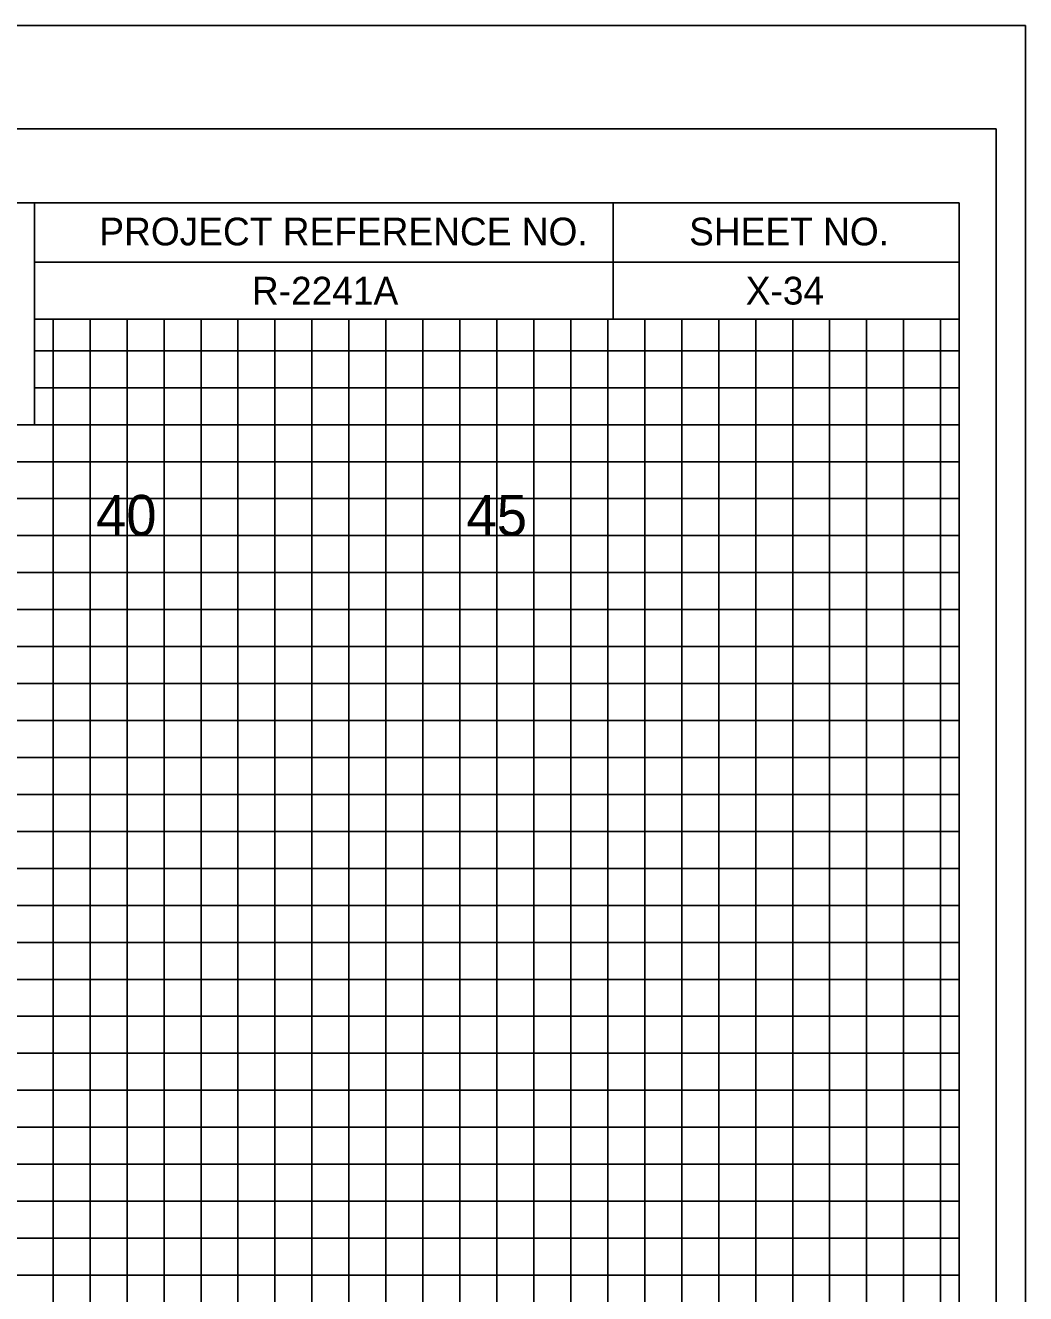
# Model space of a CAD drawing. Extents: x -4 to 103, y -2 to 6583.
# Drawn here: x 89.88 to 103.4, y 2387.47 to 2404.62 of the extents above; entities that cross this region are included whole.
import ezdxf

# ---------------------------------------------------------------- set-up
doc = ezdxf.new("R2010")
doc.units = 0
for name, color, linetype in [('Prop XS Offset Labels', 7, 'Continuous'), ('Prop XS Project Number', 7, 'Continuous'), ('Prop XS Sheet Number', 7, 'Continuous'), ('Sheet Cross Section CELL', 7, 'Continuous'), ('Sheet Cross Section Grid Major CELL', 7, 'Continuous'), ('Sheet Cross Section Grid Middle CELL', 7, 'Continuous'), ('Sheet Cutting Line CELL', 7, 'Continuous'), ('Sheet DOT Grid CELL', 7, 'Continuous'), ('Sheet Plot Border Inside CELL', 7, 'Continuous'), ('Sheet Plot Border Outside CELL', 7, 'Continuous')]:
    doc.layers.add(name, color=color, linetype=linetype)

msp = doc.modelspace()

# ---------------------------------------------------------------- linework, layer by layer
at = {"layer": 'Sheet Cross Section CELL'}
for p, q in [((90, 2402.225), (102.5, 2402.225)), ((90, 2402.225), (102.5, 2402.225)), ((97.825, 2400.65), (97.825, 2402.225)), ((101.875, 2402.225), (101.875, 2402.225)), ((102.5, 2402.225), (102.5, 2402.225)), ((102.5, 2400.65), (102.5, 2402.225)), ((102.5, 2402.225), (102.5, 2402.225)), ((102.5, 2402.225), (102.5, 2402.225)), ((102.5, 2400.65), (102.5, 2402.225)), ((90, 2401.425), (102.5, 2401.425)), ((90, 2400.65), (102.5, 2400.65)), ((99.4, 2400.65), (99.4, 2400.65)), ((99.4, 2400.65), (99.4, 2400.65))]:
    msp.add_line(p, q, dxfattribs=at)
for points in [[(102.5, 2402.225), (0, 2402.225), (0, 2337.225), (102.5, 2337.225)], [(83.75, 2402.225), (90, 2402.225), (90, 2399.225), (83.75, 2399.225)]]:
    msp.add_lwpolyline(points, close=True, dxfattribs=at)
at = {"layer": 'Sheet Cross Section Grid Major CELL'}
for points in [[(91.25, 2337.225), (91.25, 2400.65), (93.75, 2400.65), (93.75, 2337.225)], [(96.25, 2337.225), (96.25, 2400.65), (98.75, 2400.65), (98.75, 2337.225)], [(101.25, 2337.225), (101.25, 2400.65)], [(90, 2399.725), (102.5, 2399.725)], [(0, 2394.725), (102.5, 2394.725), (102.5, 2397.225), (0, 2397.225)], [(0, 2389.725), (102.5, 2389.725), (102.5, 2392.225), (0, 2392.225)]]:
    msp.add_lwpolyline(points, dxfattribs=at)
at = {"layer": 'Sheet Cross Section Grid Middle CELL'}
for points in [[(90.25, 2337.225), (90.25, 2400.65), (90.75, 2400.65), (90.75, 2337.225)], [(91.75, 2337.225), (91.75, 2400.65), (92.25, 2400.65), (92.25, 2337.225)], [(92.75, 2337.225), (92.75, 2400.65), (93.25, 2400.65), (93.25, 2337.225)], [(94.25, 2337.225), (94.25, 2400.65), (94.75, 2400.65), (94.75, 2337.225)], [(95.25, 2337.225), (95.25, 2400.65), (95.75, 2400.65), (95.75, 2337.225)], [(96.75, 2337.225), (96.75, 2400.65), (97.25, 2400.65), (97.25, 2337.225)], [(97.75, 2337.225), (97.75, 2400.65), (98.25, 2400.65), (98.25, 2337.225)], [(99.25, 2337.225), (99.25, 2400.65), (99.75, 2400.65), (99.75, 2337.225)], [(100.25, 2337.225), (100.25, 2400.65)], [(100.25, 2400.65), (100.75, 2400.65), (100.75, 2337.225), (101.75, 2337.225), (101.75, 2400.65), (102.25, 2400.65), (102.25, 2337.225)], [(102.5, 2399.225), (102.5, 2400.225), (90, 2400.225)], [(0, 2398.725), (102.5, 2398.725), (102.5, 2399.225), (0, 2399.225)], [(0, 2397.725), (102.5, 2397.725), (102.5, 2398.225), (0, 2398.225)], [(0, 2396.225), (102.5, 2396.225), (102.5, 2396.725), (0, 2396.725)], [(0, 2395.225), (102.5, 2395.225), (102.5, 2395.725), (0, 2395.725)], [(0, 2393.725), (102.5, 2393.725), (102.5, 2394.225), (0, 2394.225)], [(0, 2392.725), (102.5, 2392.725), (102.5, 2393.225), (0, 2393.225)], [(0, 2391.225), (102.5, 2391.225), (102.5, 2391.725), (0, 2391.725)], [(0, 2390.225), (102.5, 2390.225), (102.5, 2390.725), (0, 2390.725)], [(0, 2388.725), (102.5, 2388.725), (102.5, 2389.225), (0, 2389.225)], [(0, 2387.725), (102.5, 2387.725), (102.5, 2388.225), (0, 2388.225)]]:
    msp.add_lwpolyline(points, dxfattribs=at)
at = {"layer": 'Sheet Cutting Line CELL'}
msp.add_line((-3.5, 2404.625), (103.4, 2404.625), dxfattribs=at)
at = {"layer": 'Sheet DOT Grid CELL'}
for p, q in [((91.25, 2337.225), (91.25, 2400.65)), ((93.75, 2337.225), (93.75, 2400.65)), ((96.25, 2337.225), (96.25, 2400.65)), ((98.75, 2337.225), (98.75, 2400.65)), ((101.25, 2337.225), (101.25, 2400.65)), ((90, 2399.725), (102.5, 2399.725)), ((0, 2397.225), (102.5, 2397.225)), ((0, 2394.725), (102.5, 2394.725)), ((0, 2392.225), (102.5, 2392.225)), ((0, 2389.725), (102.5, 2389.725))]:
    msp.add_line(p, q, dxfattribs=at)
at = {"layer": 'Sheet Plot Border Inside CELL'}
msp.add_lwpolyline([(103, 2403.225), (-2.8, 2403.225), (-2.8, 2336.225), (103, 2336.225)], close=True, dxfattribs=at)
at = {"layer": 'Sheet Plot Border Outside CELL'}
msp.add_lwpolyline([(103.4, 2404.625), (-3.5, 2404.625), (-3.5, 2334.8), (103.4, 2334.8)], close=True, dxfattribs=at)

# ---------------------------------------------------------------- texts
at = {"layer": 'Prop XS Offset Labels'}
for s, p in [('40', (90.831, 2397.725)), ('45', (95.84, 2397.725))]:
    msp.add_text(s, height=0.55, dxfattribs=at).set_placement(p)
at = {"layer": 'Prop XS Project Number'}
msp.add_text('R-2241A', height=0.375, dxfattribs=at).set_placement((92.938, 2400.85))
at = {"layer": 'Prop XS Sheet Number'}
msp.add_text('X-34', height=0.375, dxfattribs=at).set_placement((99.616, 2400.85))
at = {"layer": 'Sheet Cross Section CELL'}
for s, p in [('PROJECT REFERENCE NO.', (90.875, 2401.65)), ('SHEET NO.', (98.85, 2401.65))]:
    msp.add_text(s, height=0.375, dxfattribs=at).set_placement(p)

doc.saveas('drawing.dxf')
